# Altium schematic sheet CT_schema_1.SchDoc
size 574 x 546 mm
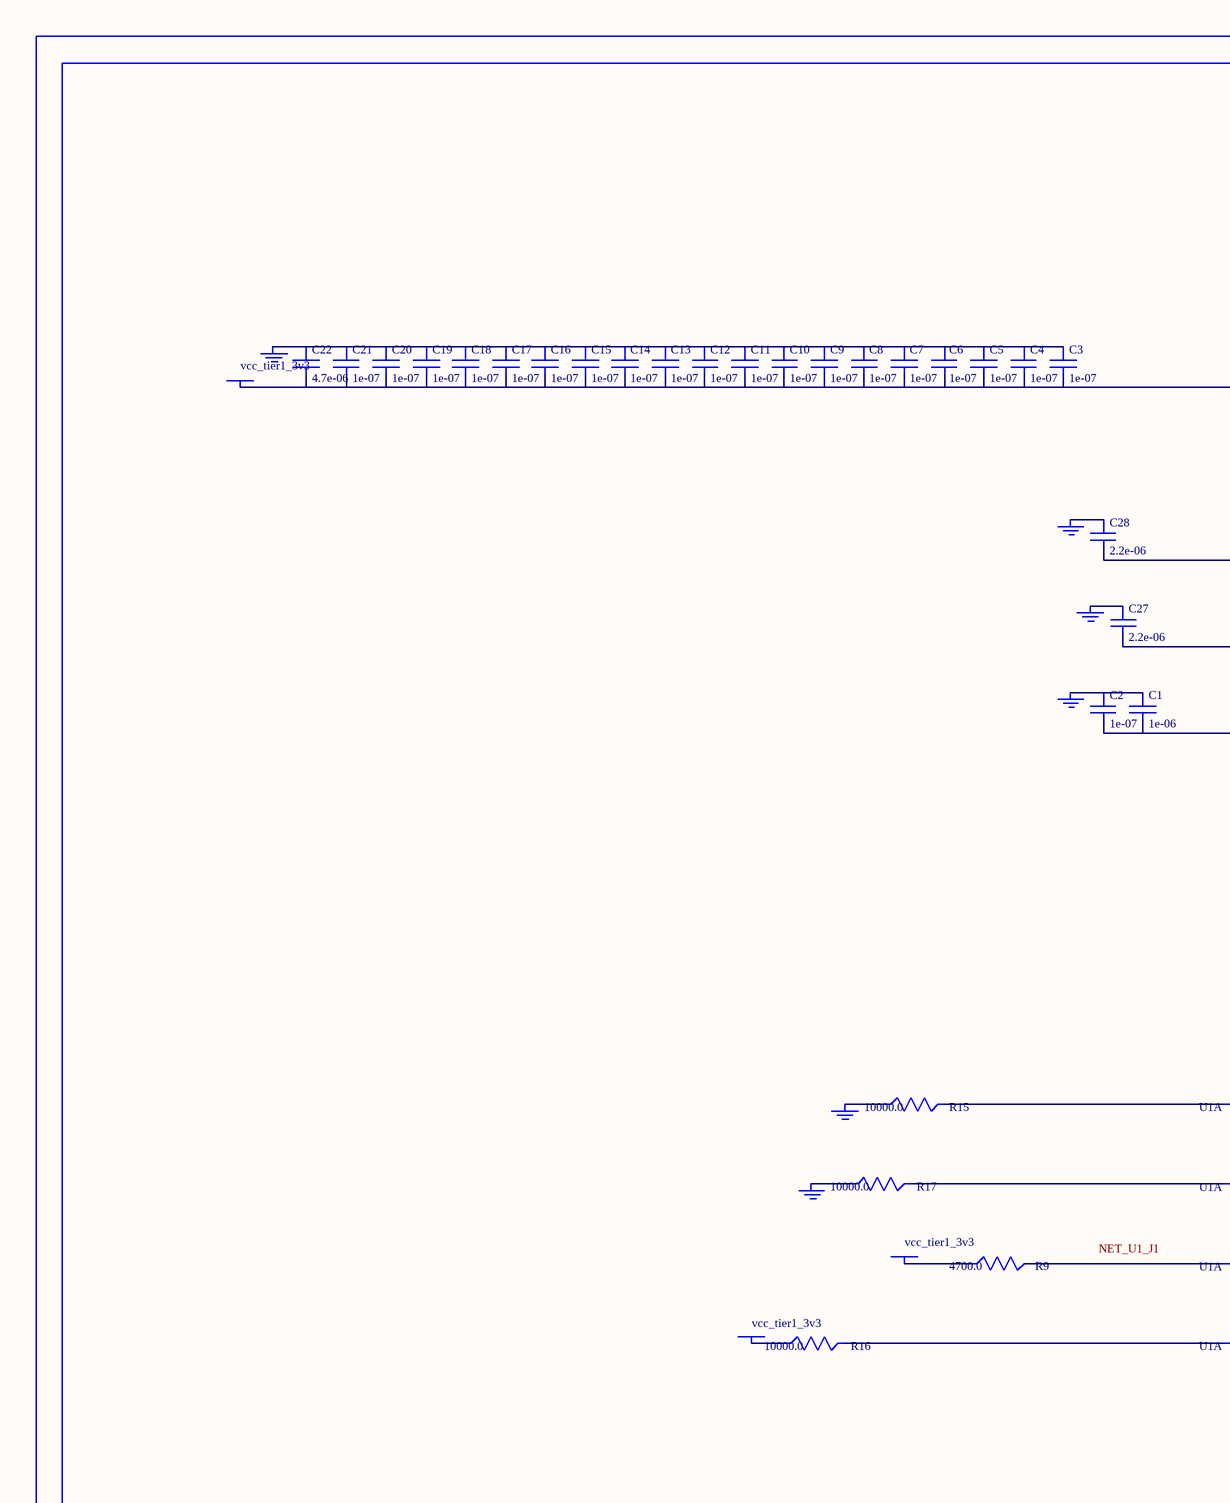
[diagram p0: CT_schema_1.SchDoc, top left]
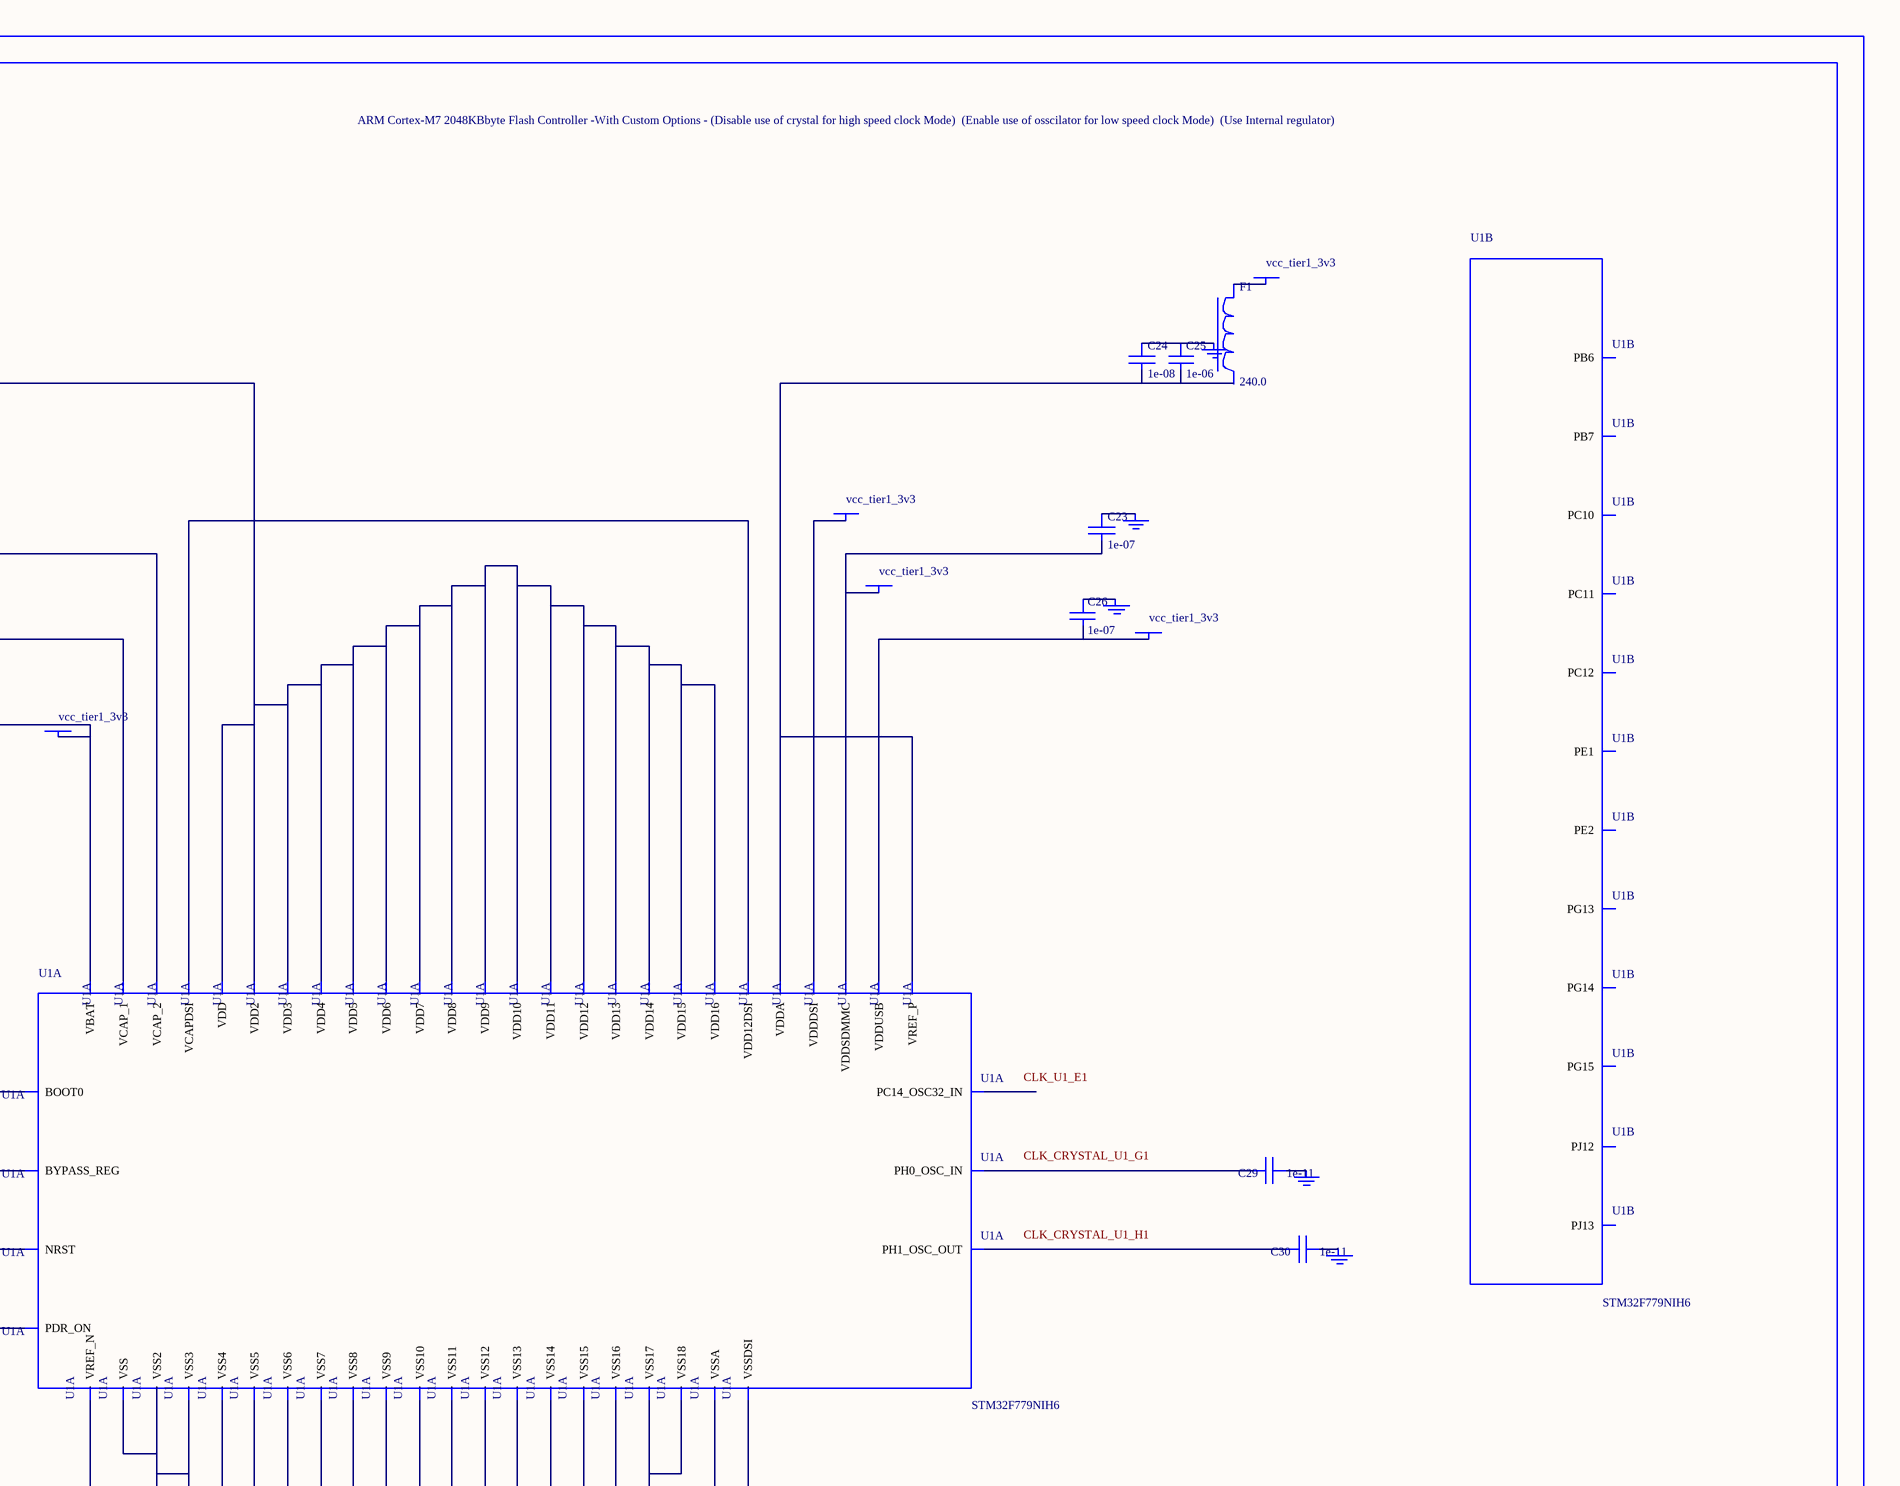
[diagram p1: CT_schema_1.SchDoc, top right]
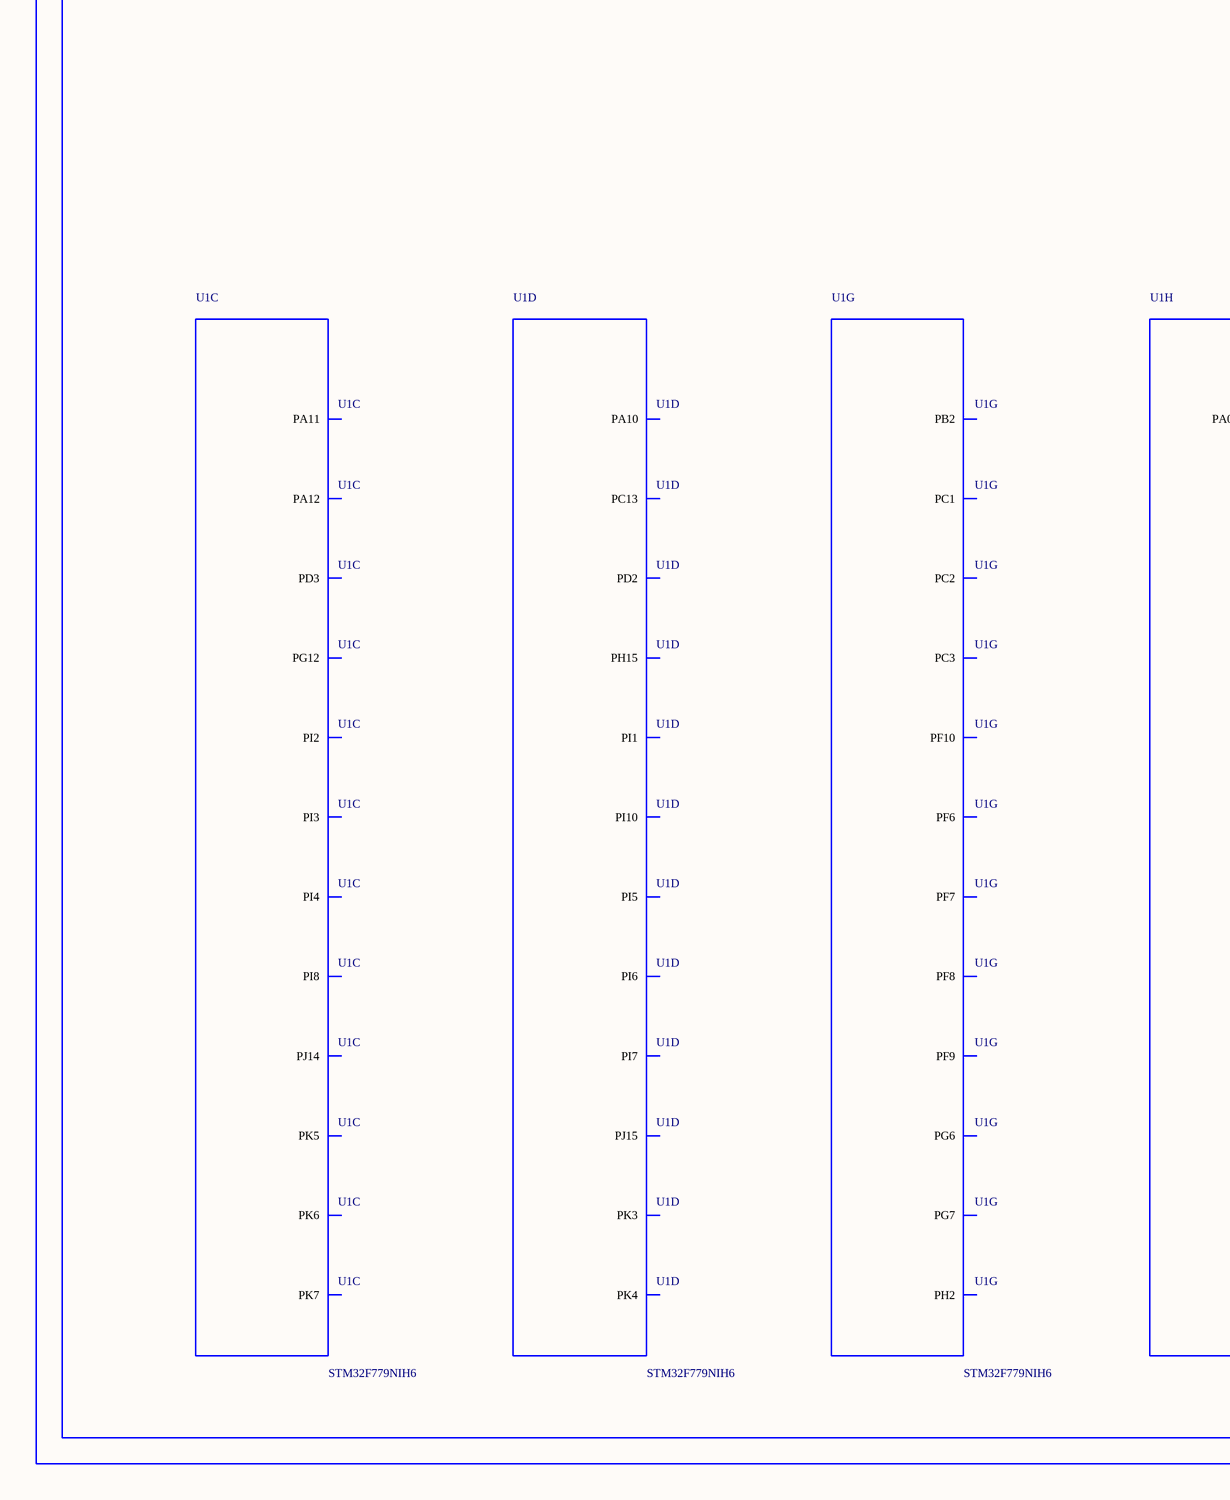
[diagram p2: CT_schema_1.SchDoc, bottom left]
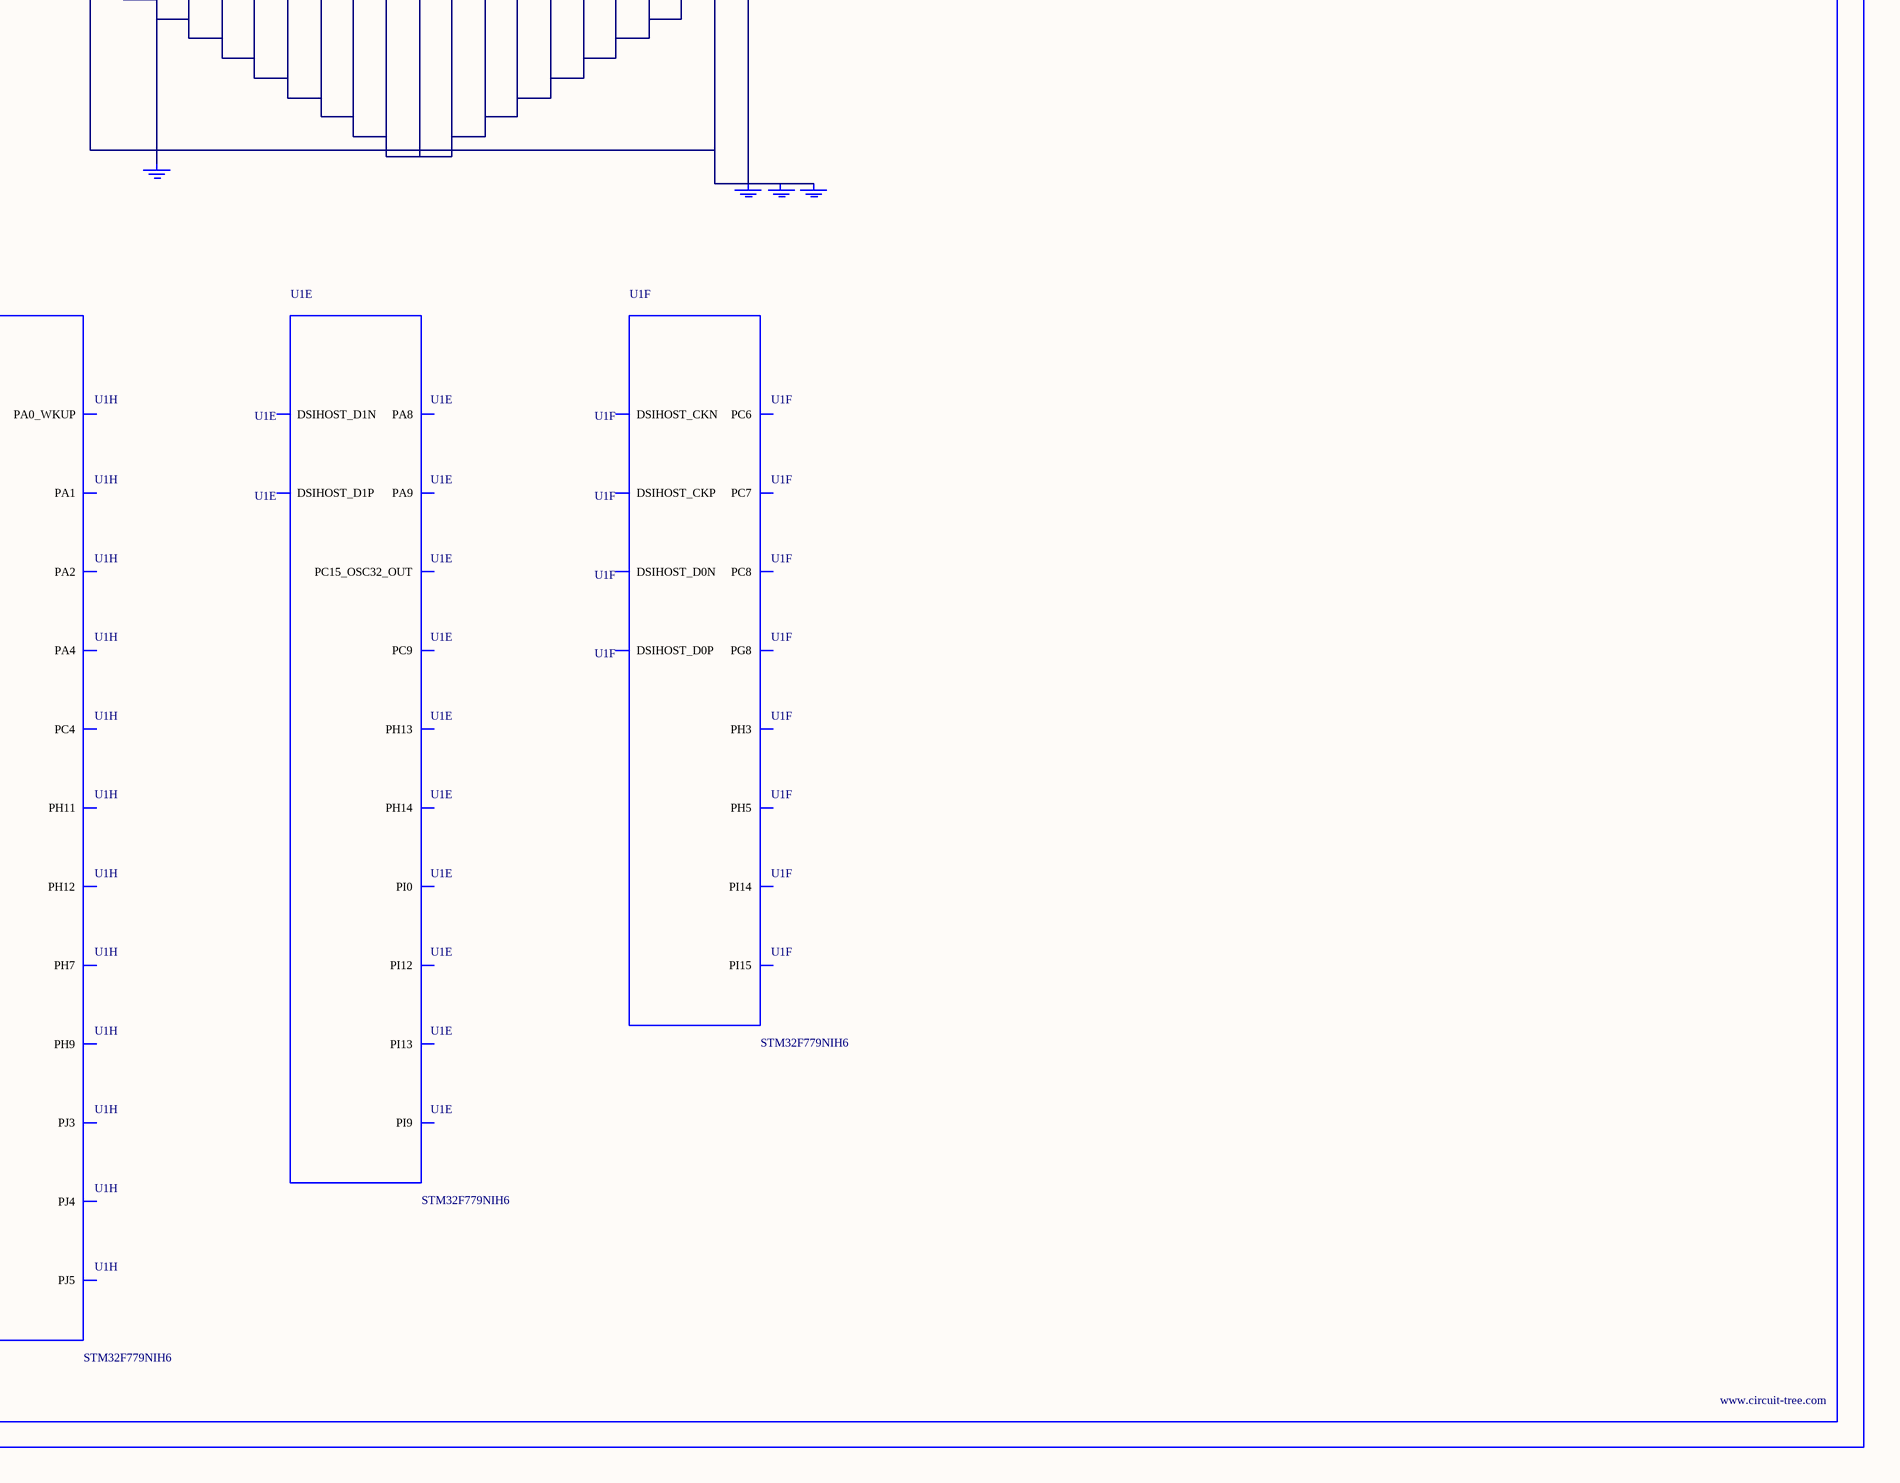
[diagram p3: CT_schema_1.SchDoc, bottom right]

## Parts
BORDER0  (no value)
C1  1e-06  [C0603]
C2  1e-07  [C0603]
C3  1e-07  [C0603]
C4  1e-07  [C0603]
C5  1e-07  [C0603]
C6  1e-07  [C0603]
C7  1e-07  [C0603]
C8  1e-07  [C0603]
C9  1e-07  [C0603]
C10  1e-07  [C0603]
C11  1e-07  [C0603]
C12  1e-07  [C0603]
C13  1e-07  [C0603]
C14  1e-07  [C0603]
C15  1e-07  [C0603]
C16  1e-07  [C0603]
C17  1e-07  [C0603]
C18  1e-07  [C0603]
C19  1e-07  [C0603]
C20  1e-07  [C0603]
C21  1e-07  [C0603]
C22  4.7e-06  [C0603]
C23  1e-07  [C0603]
C24  1e-08  [C0603]
C25  1e-06  [C0603]
C26  1e-07  [C0603]
C27  2.2e-06  [C0603]
C28  2.2e-06  [C0603]
C29  1e-11  [C0402]
C30  1e-11  [C0402]
F1  240.0  [L0603]
GND_INSTANCE_0_0  (no value)
GND_INSTANCE_0_1  (no value)
GND_INSTANCE_0_2  (no value)
GND_INSTANCE_0_3  (no value)
GND_INSTANCE_0_4  (no value)
GND_INSTANCE_0_5  (no value)
GND_INSTANCE_0_6  (no value)
GND_INSTANCE_0_7  (no value)
GND_INSTANCE_0_8  (no value)
GND_INSTANCE_0_9  (no value)
GND_INSTANCE_0_10  (no value)
GND_INSTANCE_0_11  (no value)
GND_INSTANCE_0_12  (no value)
GND_INSTANCE_0_13  (no value)
GND_INSTANCE_0_14  (no value)
POWER_INSTANCE_0_0  vcc_tier1_3v3
POWER_INSTANCE_0_1  vcc_tier1_3v3
POWER_INSTANCE_0_2  vcc_tier1_3v3
POWER_INSTANCE_0_3  vcc_tier1_3v3
POWER_INSTANCE_0_4  vcc_tier1_3v3
POWER_INSTANCE_0_5  vcc_tier1_3v3
POWER_INSTANCE_0_6  vcc_tier1_3v3
POWER_INSTANCE_0_7  vcc_tier1_3v3
R9  4700.0  [R0603]
R15  10000.0  [R0603]
R16  10000.0  [R0603]
R17  10000.0  [R0603]
U1  STM32F779NIH6  [TFBGA216]  (parts A,B,C,D,E,F,G,H of 16)

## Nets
NetC1_1: C1.1 C2.1 GND_INSTANCE_0_0.0(GND)
NetC1_2: C1.2 C2.2 POWER_INSTANCE_0_0.0(PWR) U1.C1(VBAT)
NetC3_1: C3.1 C4.1 C5.1 C6.1 C7.1 C8.1 C9.1 C10.1 C11.1 C12.1 C13.1 C14.1 C15.1 C16.1 C17.1 C18.1 C19.1 C20.1 C21.1 C22.1 GND_INSTANCE_0_2.0(GND)
NetC3_2: C3.2 C4.2 C5.2 C6.2 C7.2 C8.2 C9.2 C10.2 C11.2 C12.2 C13.2 C14.2 C15.2 C16.2 C17.2 C18.2 C19.2 C20.2 C21.2 C22.2 POWER_INSTANCE_0_2.0(PWR) U1.E7(VDD2) U1.E8(VDD3) U1.E10(VDD) U1.F4(VDD5) U1.F5(VDD6) U1.F11(VDD4) U1.G5(VDD7) U1.H5(VDD8) U1.J5(VDD10) U1.J11(VDD9) U1.K5(VDD12) U1.K11(VDD11) U1.L7(VDD14) U1.L8(VDD15) U1.L9(VDD16) U1.L10(VDD13)
NetC23_1: C23.1 GND_INSTANCE_0_4.0(GND)
NetC23_2: C23.2 POWER_INSTANCE_0_3.0(PWR) U1.E9(VDDSDMMC)
NetC24_1: C24.1 C25.1 GND_INSTANCE_0_1.0(GND)
NetC24_2: C24.2 C25.2 U1.P1(VREF_P) U1.R1(VDDA)
NetC26_1: C26.1 GND_INSTANCE_0_5.0(GND)
NetC26_2: C26.2 POWER_INSTANCE_0_5.0(PWR) U1.G11(VDDUSB)
NetC27_1: C27.1 GND_INSTANCE_0_7.0(GND)
NetC27_2: C27.2 U1.L11(VCAP_1)
NetC28_1: C28.1 GND_INSTANCE_0_8.0(GND)
NetC28_2: C28.2 U1.E11(VCAP_2)
NetC29_1: C29.1 GND_INSTANCE_0_9.0(GND)
NetC29_2: C29.2 U1.G1(PH0_OSC_IN)
NetC30_1: C30.1 GND_INSTANCE_0_10.0(GND)
NetC30_2: C30.2 U1.H1(PH1_OSC_OUT)
NetF1_1: F1.1 POWER_INSTANCE_0_1.0(PWR)
NetGND_INSTANCE_0_3_0: GND_INSTANCE_0_3.0(GND) R15.1
NetGND_INSTANCE_0_6_0: GND_INSTANCE_0_6.0(GND) R17.1
NetGND_INSTANCE_0_11_0: GND_INSTANCE_0_11.0(GND) GND_INSTANCE_0_12.0(GND) GND_INSTANCE_0_13.0(GND) U1.G12(VSSDSI) U1.M1(VSSA) U1.N1(VREF_N)
NetGND_INSTANCE_0_14_0: GND_INSTANCE_0_14.0(GND) U1.F2(VSS2) U1.F6(VSS3) U1.F7(VSS4) U1.F8(VSS5) U1.F9(VSS6) U1.F10(VSS) U1.G6(VSS8) U1.G10(VSS7) U1.H6(VSS10) U1.H10(VSS9) U1.J6(VSS12) U1.J10(VSS11) U1.K6(VSS14) U1.K7(VSS15) U1.K8(VSS16) U1.K9(VSS17) U1.K10(VSS13) U1.L6(VSS18)
NetPOWER_INSTANCE_0_4_0: POWER_INSTANCE_0_4.0(PWR) R16.1
NetPOWER_INSTANCE_0_6_0: POWER_INSTANCE_0_6.0(PWR) U1.H11(VDDDSI)
NetPOWER_INSTANCE_0_7_0: POWER_INSTANCE_0_7.0(PWR) R9.1
NetR9_2: R9.2 U1.J1(NRST)
NetR15_2: R15.2 U1.E6(BOOT0)
NetR16_2: R16.2 U1.E5(PDR_ON)
NetR17_2: R17.2 U1.L5(BYPASS_REG)
NetU1_G13: U1.G13(VDD12DSI) U1.K12(VCAPDSI)

Not connected (* = marked no-connect by the designer): F1 2; U1 A3(PE2) A4(PG14) A5(PE1) A12(PC12) B3(PG13) B5(PB7) B6(PB6) B7(PG15) B9(PJ13) B10(PJ12) B13(PC11) B14(PC10) B15(PA12) C2(PI8) C3(PI4) C4(PK7) C5(PK6) C6(PK5) C7(PG12) C9(PJ14) C11(PD3) C13(PI3) C14(PI2) C15(PA11) D1(PC13) D3(PI5) D4(PI7) D5(PI10) D6(PI6) D7(PK4) D8(PK3) D10(PJ15) D12(PD2) D13(PH15) D14(PI1) D15(PA10) E1(PC14_OSC32_IN) E3(PI12) E4(PI9) E12(PH13) E13(PH14) E14(PI0) E15(PA9) F1(PC15_OSC32_OUT) F12(DSIHOST_D1P) F13(DSIHOST_D1N) F14(PC9) F15(PA8) G3(PI13) G4(PI15) G14(PC8) G15(PC7) H3(PI14) H12(DSIHOST_CKP) H13(DSIHOST_CKN) H14(PG8) H15(PC6) J3(PH5) J4(PH3) J12(DSIHOST_D0P) J13(DSIHOST_D0N) J14(PG7) J15(PG6) K1(PF7) K2(PF6) K4(PH2) L1(PF10) L2(PF9) L3(PF8) L4(PC3) M3(PC1) M4(PC2) M5(PB2) M9(PJ4) M14(PJ5) M15(PH12) N2(PA1) N3(PA0_WKUP) N4(PA4) N5(PC4) N8(PJ3) N13(PH7) N14(PH9) N15(PH11) P2(PA2)

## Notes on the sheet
- Labels drawn without touching a wire or pin: CLK_CRYSTAL_U1_G1, CLK_CRYSTAL_U1_H1, CLK_U1_E1, NET_U1_J1

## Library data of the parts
BORDER0 = BORDER_PAGE0
C1 C25 = C0603C105K3RACTU
C2-C21 C23 C26 = 06035C104K4Z2A
C22 = GRM188R6YA475KE15D
C24 = 06035C103K4Z2A
C27 C28 = C0603C225K8RACTU
C29 C30 = C0402C100K3GACTU
F1 = Z0603C241ASMST
GND_INSTANCE_0_0-GND_INSTANCE_0_14 = GND
POWER_INSTANCE_0_0-POWER_INSTANCE_0_7 = PWR
R9 = RC0603JR-074K7L
R15-R17 = RC0603JR-0710KL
